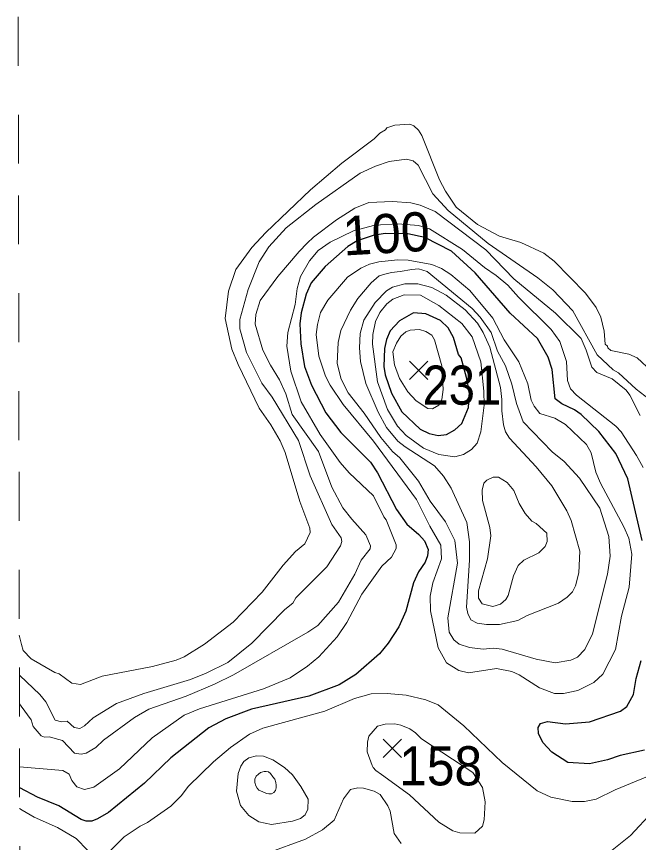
# Model space of a CAD drawing. Extents: x 474.5 to 500, y 7345.7 to 7373.4.
# Drawn here: x 474.546 to 475.818, y 7356.191 to 7357.879 of the extents above; entities that cross this region are included whole.
import ezdxf
from ezdxf.enums import TextEntityAlignment as Align

# ---------------------------------------------------------------- set-up
doc = ezdxf.new("R2010")
doc.units = 0
doc.header["$LTSCALE"] = 0.032
doc.linetypes.add('SHORT_DASHED', pattern=[2.7, 1.5, -1.2])
for name, color, linetype, lineweight in [('1', 7, 'Continuous', 25), ('2', 7, 'Continuous', 13), ('21', 7, 'Continuous', 25), ('22', 7, 'SHORT_DASHED', 13)]:
    doc.layers.add(name, color=color, linetype=linetype, lineweight=lineweight)
doc.layers.add('61', color=7, linetype='Continuous')

msp = doc.modelspace()

# ---------------------------------------------------------------- linework, layer by layer
at = {"layer": '1'}
for points in [[(475.8254, 7356.8079), (475.7963, 7356.9343), (475.7714, 7356.9858), (475.737, 7357.0305), (475.7007, 7357.0654), (475.6867, 7357.0751), (475.6613, 7357.0874), (475.6478, 7357.0975), (475.6411, 7357.1574), (475.6332, 7357.1824), (475.6113, 7357.2207), (475.5555, 7357.2725), (475.4841, 7357.3551), (475.4354, 7357.3994), (475.3811, 7357.4268), (475.3464, 7357.4348), (475.2997, 7357.4352), (475.2753, 7357.4312), (475.2428, 7357.4202), (475.2238, 7357.4089), (475.1773, 7357.3679), (475.1485, 7357.3348), (475.1382, 7357.3113), (475.1278, 7357.273), (475.1254, 7357.2507), (475.1272, 7357.2097), (475.1351, 7357.1636), (475.1495, 7357.1253), (475.1783, 7357.0687), (475.2092, 7357.0284), (475.2699, 7356.9678), (475.2839, 7356.946), (475.3229, 7356.8714), (475.3441, 7356.8411), (475.3684, 7356.8206), (475.3803, 7356.8072), (475.3877, 7356.7894), (475.3862, 7356.7768), (475.3815, 7356.7641), (475.3678, 7356.7438), (475.3577, 7356.7213), (475.342, 7356.6638), (475.3279, 7356.6314), (475.3058, 7356.5981), (475.288, 7356.5763), (475.2396, 7356.5342), (475.2057, 7356.5132), (475.1441, 7356.4903), (475.0267, 7356.4634), (474.9739, 7356.4437), (474.9392, 7356.4254), (474.8618, 7356.364), (474.8076, 7356.3121), (474.7345, 7356.2523), (474.7119, 7356.2391), (474.7001, 7356.2349), (474.6887, 7356.2349), (474.6783, 7356.2379), (474.6326, 7356.2659), (474.5887, 7356.2838), (474.5526, 7356.3028), (474.5524, 7356.3029)], [(475.8302, 7356.3797), (475.7806, 7356.369), (475.7547, 7356.3601), (475.7175, 7356.3515), (475.6732, 7356.3547), (475.6409, 7356.3756), (475.622, 7356.3955), (475.6135, 7356.414), (475.6129, 7356.4258), (475.6178, 7356.4342), (475.6319, 7356.4383), (475.6684, 7356.4336), (475.7178, 7356.4375), (475.7812, 7356.4596), (475.7943, 7356.4692), (475.8074, 7356.4936), (475.813, 7356.5263), (475.8235, 7356.5626)]]:
    msp.add_lwpolyline(points, dxfattribs=at)
msp.add_lwpolyline([(475.3289, 7357.2571), (475.3099, 7357.2366), (475.3024, 7357.2185), (475.2984, 7357.2006), (475.2972, 7357.1634), (475.3001, 7357.1464), (475.3125, 7357.1091), (475.334, 7357.0712), (475.3713, 7357.0357), (475.3897, 7357.027), (475.4082, 7357.0223), (475.425, 7357.0243), (475.4426, 7357.0341), (475.4564, 7357.047), (475.47, 7357.0798), (475.4721, 7357.111), (475.4665, 7357.1411), (475.455, 7357.1816), (475.4501, 7357.1883), (475.4399, 7357.2226), (475.4284, 7357.2424), (475.4128, 7357.2574), (475.383, 7357.2711), (475.3577, 7357.2735)], close=True, dxfattribs=at)
at = {"layer": '2'}
for points in [[(475.8443, 7357.1541), (475.8152, 7357.181), (475.798, 7357.1889), (475.7616, 7357.196), (475.7549, 7357.2017), (475.7545, 7357.2051), (475.75, 7357.2092), (475.7475, 7357.236), (475.7406, 7357.2643), (475.7315, 7357.2842), (475.7096, 7357.3131), (475.6457, 7357.3787), (475.6245, 7357.395), (475.5774, 7357.4172), (475.5339, 7357.4296), (475.4889, 7357.454), (475.4452, 7357.489), (475.4231, 7357.5216), (475.4112, 7357.5451), (475.3749, 7357.6352), (475.3682, 7357.6466), (475.3584, 7357.6555), (475.35, 7357.6588), (475.3197, 7357.6565), (475.3035, 7357.651), (475.3008, 7357.647), (475.2887, 7357.6404), (475.2771, 7357.6287), (475.211, 7357.5793), (475.1472, 7357.5244), (475.0561, 7357.4373), (475.0274, 7357.407), (474.9944, 7357.3619), (474.9794, 7357.3177), (474.973, 7357.2617), (474.9866, 7357.1991), (474.9991, 7357.1677), (475.0422, 7357.0784), (475.0663, 7357.0446), (475.0853, 7357.0114), (475.0954, 7356.9877), (475.1255, 7356.8876), (475.1459, 7356.833), (475.1467, 7356.8245), (475.1355, 7356.8012), (475.1167, 7356.7855), (475.0912, 7356.7576)], [(474.5519, 7356.5334), (474.5532, 7356.5322), (474.5937, 7356.4937), (474.606, 7356.4782), (474.6249, 7356.4411), (474.6381, 7356.4377), (474.6496, 7356.4391), (474.6637, 7356.4259), (474.6754, 7356.4241), (474.6851, 7356.4294), (474.7027, 7356.446), (474.7508, 7356.4753), (474.8063, 7356.4952), (474.902, 7356.524), (474.9339, 7356.5368), (474.9784, 7356.5591), (475.0276, 7356.5982), (475.0944, 7356.6674), (475.1108, 7356.6799), (475.1172, 7356.6911), (475.1803, 7356.7543), (475.2083, 7356.7974), (475.2115, 7356.8059), (475.2098, 7356.8133), (475.1905, 7356.8407), (475.1464, 7356.9401), (475.123, 7357.0125), (475.069, 7357.1008), (475.0476, 7357.1296), (475.0164, 7357.1922), (475.0025, 7357.2403), (475.0029, 7357.2595), (475.0201, 7357.321), (475.042, 7357.3773), (475.062, 7357.408), (475.0977, 7357.447), (475.1582, 7357.4947), (475.2486, 7357.5586), (475.2803, 7357.5731), (475.3083, 7357.5824), (475.3434, 7357.587), (475.3573, 7357.584), (475.3672, 7357.5749), (475.3973, 7357.5162), (475.4288, 7357.4824), (475.5107, 7357.4149), (475.6119, 7357.3447), (475.6426, 7357.3202), (475.6837, 7357.2775), (475.7334, 7357.1873), (475.766, 7357.157), (475.7768, 7357.1503), (475.8128, 7357.1174), (475.8398, 7357.0968)], [(475.4023, 7357.48), (475.3716, 7357.493), (475.3527, 7357.4977), (475.315, 7357.5009), (475.2665, 7357.4985), (475.2376, 7357.4872), (475.2006, 7357.4631), (475.1535, 7357.4276), (475.1403, 7357.4158), (475.1241, 7357.3984), (475.0801, 7357.3477), (475.0446, 7357.2981), (475.0352, 7357.2701), (475.0344, 7357.2502), (475.0495, 7357.1968), (475.0654, 7357.1661), (475.0841, 7357.1366), (475.097, 7357.1075), (475.1094, 7357.0656), (475.1638, 7356.9901), (475.1907, 7356.9173), (475.2133, 7356.8748), (475.2314, 7356.8515), (475.2603, 7356.8194), (475.2697, 7356.7974), (475.2694, 7356.7911), (475.251, 7356.7681), (475.2377, 7356.7396), (475.2047, 7356.6819), (475.1622, 7356.6347), (475.1418, 7356.6209), (474.9895, 7356.5335), (474.9509, 7356.5142), (474.8929, 7356.49), (474.8164, 7356.4637), (474.7873, 7356.4467), (474.7241, 7356.4), (474.7086, 7356.3852), (474.6884, 7356.3736), (474.6784, 7356.3714), (474.6645, 7356.3738), (474.6403, 7356.3992), (474.6129, 7356.4071), (474.6031, 7356.4065), (474.5963, 7356.409), (474.5804, 7356.4282), (474.5764, 7356.4416), (474.5558, 7356.4695), (474.5521, 7356.4746)], [(475.821, 7357.0635), (475.8004, 7357.105), (475.7928, 7357.115), (475.7637, 7357.1386), (475.7327, 7357.1514), (475.7224, 7357.1619), (475.7112, 7357.1968), (475.7005, 7357.2209), (475.6484, 7357.2723), (475.5633, 7357.3429), (475.506, 7357.4016), (475.4023, 7357.48)], [(474.5523, 7356.3459), (474.6409, 7356.3379), (474.6538, 7356.3305), (474.6593, 7356.318), (474.6696, 7356.3047), (474.6849, 7356.2996), (474.7041, 7356.3039), (474.7566, 7356.3416), (474.8234, 7356.4052), (474.889, 7356.4509), (474.92, 7356.464), (475.0509, 7356.5053), (475.1058, 7356.5278), (475.1414, 7356.5512), (475.1644, 7356.5707), (475.2016, 7356.611), (475.2217, 7356.6407), (475.252, 7356.6981), (475.2933, 7356.7554), (475.3129, 7356.7743), (475.3221, 7356.792), (475.3223, 7356.7992), (475.3022, 7356.8505), (475.2972, 7356.8563), (475.2759, 7356.899), (475.2263, 7356.946), (475.2082, 7356.9673), (475.1667, 7357.0249), (475.1283, 7357.0913), (475.107, 7357.1542), (475.0991, 7357.2049), (475.1008, 7357.2333), (475.1157, 7357.2904), (475.1198, 7357.3227), (475.1269, 7357.3475), (475.1455, 7357.3793), (475.1631, 7357.4006), (475.1874, 7357.4175), (475.2351, 7357.441), (475.2786, 7357.452), (475.326, 7357.4552), (475.3683, 7357.4516), (475.3907, 7357.4447), (475.458, 7357.4028), (475.5032, 7357.3655), (475.527, 7357.3497), (475.5508, 7357.33), (475.5722, 7357.3052), (475.6392, 7357.239), (475.6573, 7357.2144), (475.6704, 7357.1741), (475.6726, 7357.1352), (475.6791, 7357.1178), (475.6908, 7357.1051), (475.7718, 7357.0418), (475.7827, 7357.0301), (475.814, 7356.9818), (475.8271, 7356.9574)], [(475.0912, 7356.7576), (475.0487, 7356.7024), (474.9889, 7356.6409), (474.9306, 7356.5962), (474.889, 7356.5702), (474.8723, 7356.5633), (474.8239, 7356.5505), (474.7211, 7356.5309), (474.6772, 7356.5137), (474.6595, 7356.5165), (474.6333, 7356.5355), (474.6244, 7356.5385), (474.5761, 7356.5664), (474.5597, 7356.583), (474.5566, 7356.5955), (474.5518, 7356.6148)], [(474.7339, 7356.1709), (474.7659, 7356.2024), (474.799, 7356.2245), (474.8137, 7356.2317), (474.8614, 7356.2655), (474.8826, 7356.2866), (474.8981, 7356.306), (474.9486, 7356.3557), (474.9837, 7356.3853), (475.0222, 7356.4126), (475.0498, 7356.4248), (475.1766, 7356.4597), (475.2375, 7356.4854), (475.2711, 7356.4949), (475.3038, 7356.4957), (475.3429, 7356.4918), (475.3828, 7356.4823), (475.4083, 7356.4723), (475.4608, 7356.4291), (475.5391, 7356.3547), (475.6108, 7356.2968), (475.6386, 7356.284), (475.6824, 7356.2748), (475.7075, 7356.2748), (475.7311, 7356.2796), (475.7702, 7356.2985), (475.8673, 7356.3391)], [(475.3323, 7356.1889), (475.3186, 7356.2096), (475.3104, 7356.2548), (475.3055, 7356.2663), (475.2896, 7356.289), (475.2775, 7356.2956), (475.2556, 7356.3019), (475.244, 7356.3027), (475.2293, 7356.2996), (475.2145, 7356.2801), (475.1955, 7356.2364), (475.1719, 7356.2168), (475.1371, 7356.1981), (475.0585, 7356.1692)], [(474.5524, 7356.2602), (474.5574, 7356.2573), (474.5823, 7356.2426), (474.6301, 7356.222), (474.6682, 7356.1992), (474.6922, 7356.1746)], [(475.847, 7356.2546), (475.8012, 7356.2055), (475.7536, 7356.1674)]]:
    msp.add_lwpolyline(points, dxfattribs=at)
for points in [[(475.276, 7357.0113), (475.2137, 7357.0862), (475.1874, 7357.1254), (475.1777, 7357.1438), (475.1645, 7357.1845), (475.1589, 7357.2289), (475.1613, 7357.2493), (475.1679, 7357.2737), (475.1824, 7357.299), (475.2231, 7357.3458), (475.2503, 7357.3644), (475.2681, 7357.3724), (475.287, 7357.3772), (475.325, 7357.3812), (475.3471, 7357.3805), (475.3952, 7357.3718), (475.4152, 7357.3636), (475.4343, 7357.3516), (475.4727, 7357.3187), (475.5198, 7357.2622), (475.5432, 7357.2179), (475.5733, 7357.1728), (475.5918, 7357.1281), (475.5983, 7357.0946), (475.6043, 7357.0824), (475.6162, 7357.0677), (475.6468, 7357.0579), (475.6686, 7357.0454), (475.7116, 7357.0039), (475.7213, 7356.9869), (475.7307, 7356.9478), (475.7404, 7356.9249), (475.7881, 7356.8359), (475.7979, 7356.813), (475.8042, 7356.78), (475.7986, 7356.7125), (475.7834, 7356.6533), (475.7709, 7356.5857), (475.7447, 7356.5351), (475.7265, 7356.5182), (475.6935, 7356.5017), (475.6644, 7356.4958), (475.6458, 7356.4958), (475.6157, 7356.5071), (475.5742, 7356.5334), (475.5588, 7356.5406), (475.5272, 7356.5468), (475.4706, 7356.5374), (475.4505, 7356.5426), (475.4251, 7356.5582), (475.4084, 7356.5889), (475.3926, 7356.6646), (475.3918, 7356.6942), (475.3971, 7356.7214), (475.415, 7356.7707), (475.4134, 7356.7987), (475.3909, 7356.8372), (475.3637, 7356.8917)], [(475.3301, 7356.9767), (475.3147, 7356.9898), (475.2908, 7357.0185), (475.2569, 7357.0685), (475.2244, 7357.1101), (475.2097, 7357.1374), (475.2015, 7357.17), (475.2036, 7357.2124), (475.2089, 7357.2371), (475.2289, 7357.2789), (475.2441, 7357.3028), (475.2713, 7357.3345), (475.2873, 7357.3487), (475.299, 7357.3524), (475.3129, 7357.3553), (475.3307, 7357.3578), (475.3541, 7357.3618), (475.3683, 7357.3629), (475.3858, 7357.3575), (475.4776, 7357.2819), (475.4942, 7357.2645), (475.5169, 7357.2331), (475.5296, 7357.1949), (475.5457, 7357.1647), (475.5586, 7357.1273), (475.5685, 7357.0877), (475.5818, 7357.0508), (475.6412, 7356.9889), (475.6659, 7356.9692), (475.6969, 7356.9357), (475.7387, 7356.8742), (475.7572, 7356.8159), (475.7596, 7356.7759), (475.7547, 7356.7396), (475.7237, 7356.6173), (475.7084, 7356.5852), (475.6931, 7356.5698), (475.6792, 7356.5634), (475.6476, 7356.558), (475.6085, 7356.5653), (475.5391, 7356.586), (475.5208, 7356.5883), (475.5001, 7356.586), (475.4721, 7356.5892), (475.4509, 7356.5961), (475.4403, 7356.6052), (475.4307, 7356.6208), (475.4277, 7356.6499), (475.4476, 7356.7617), (475.4422, 7356.8079), (475.423, 7356.8465), (475.392, 7356.8881), (475.368, 7356.9295)], [(475.3408, 7356.9992), (475.326, 7357.011), (475.3029, 7357.0387), (475.2854, 7357.0706), (475.2606, 7357.1291), (475.2497, 7357.1741), (475.2474, 7357.2016), (475.2489, 7357.231), (475.256, 7357.258), (475.2793, 7357.2941), (475.3027, 7357.3179), (475.3148, 7357.3259), (475.3398, 7357.3328), (475.3668, 7357.3327), (475.3952, 7357.3249), (475.4243, 7357.3096), (475.4632, 7357.2795), (475.4885, 7357.2518), (475.5001, 7357.2331), (475.5142, 7357.2032), (475.5358, 7357.1207), (475.5385, 7357.0959), (475.5381, 7357.073), (475.5418, 7357.0441), (475.546, 7357.0298), (475.5543, 7357.0173), (475.6086, 7356.9586), (475.6408, 7356.9199), (475.6715, 7356.8687), (475.6802, 7356.8487), (475.6981, 7356.7861), (475.6958, 7356.7417), (475.6892, 7356.7157), (475.6829, 7356.7032), (475.6718, 7356.692), (475.6546, 7356.6799), (475.59, 7356.655), (475.571, 7356.6449), (475.5334, 7356.6362), (475.5069, 7356.6362), (475.4881, 7356.6394), (475.4752, 7356.646), (475.4688, 7356.6587), (475.466, 7356.672), (475.4723, 7356.7681), (475.4724, 7356.8051), (475.4668, 7356.8446), (475.4351, 7356.9148), (475.4194, 7356.9397), (475.4005, 7356.9608)], [(475.274, 7357.2089), (475.2746, 7357.2287), (475.2803, 7357.2558), (475.2887, 7357.2741), (475.3035, 7357.2914), (475.3157, 7357.3009), (475.3384, 7357.3102), (475.3718, 7357.3094), (475.4099, 7357.2881), (475.4569, 7357.2516), (475.4778, 7357.2244), (475.4956, 7357.1733), (475.5019, 7357.1129), (475.5025, 7357.0845), (475.4954, 7357.0303), (475.4879, 7357.0072), (475.4767, 7356.9939), (475.4603, 7356.984), (475.4423, 7356.9793), (475.4096, 7356.984), (475.3783, 7356.9967), (475.3425, 7357.0228), (475.3254, 7357.042), (475.3046, 7357.0754), (475.2841, 7357.1323)], [(475.3321, 7357.2253), (475.3423, 7357.2343), (475.3513, 7357.2377), (475.3702, 7357.2392), (475.3828, 7357.2353), (475.3955, 7357.2274), (475.4006, 7357.2183), (475.4157, 7357.1652), (475.4183, 7357.1163), (475.4159, 7357.096), (475.4093, 7357.0843), (475.3969, 7357.0769), (475.3874, 7357.0775), (475.3636, 7357.0934), (475.3464, 7357.1115), (475.3292, 7357.1392), (475.3189, 7357.1667), (475.3159, 7357.1938), (475.3228, 7357.2113)], [(475.6089, 7356.843), (475.5999, 7356.8477), (475.5863, 7356.8629), (475.5741, 7356.8839), (475.5628, 7356.9101), (475.5495, 7356.9267), (475.5317, 7356.9376), (475.5206, 7356.9378), (475.508, 7356.9316), (475.5014, 7356.9253), (475.4982, 7356.9111), (475.4986, 7356.8899), (475.5138, 7356.8343), (475.5162, 7356.8175), (475.5091, 7356.7704), (475.4906, 7356.7054), (475.4908, 7356.6902), (475.498, 7356.6785), (475.5202, 7356.6729), (475.5356, 7356.6782), (475.5465, 7356.6874), (475.5512, 7356.6957), (475.5624, 7356.7361), (475.5715, 7356.757), (475.5833, 7356.7681), (475.6141, 7356.7828), (475.6271, 7356.7959), (475.6312, 7356.8058), (475.6305, 7356.823)], [(475.4989, 7356.3033), (475.4793, 7356.3341), (475.3739, 7356.4026), (475.3618, 7356.4154), (475.3505, 7356.4234), (475.3319, 7356.4311), (475.3194, 7356.4335), (475.2998, 7356.4327), (475.2841, 7356.4287), (475.2666, 7356.4086), (475.2637, 7356.396), (475.2634, 7356.3762), (475.2735, 7356.3481), (475.2753, 7356.3443), (475.2809, 7356.3382), (475.2922, 7356.3303), (475.3498, 7356.2881), (475.4093, 7356.2325), (475.4382, 7356.2152), (475.4523, 7356.2109), (475.4832, 7356.2102), (475.4986, 7356.2246), (475.5026, 7356.2373), (475.5042, 7356.2744)], [(475.0108, 7356.3566), (475.0211, 7356.3642), (475.0367, 7356.3681), (475.0514, 7356.3674), (475.0705, 7356.36), (475.0938, 7356.3445), (475.1103, 7356.3296), (475.1277, 7356.3058), (475.1426, 7356.2793), (475.142, 7356.2591), (475.1363, 7356.2476), (475.1266, 7356.2403), (475.1105, 7356.2343), (475.0674, 7356.2278), (475.0418, 7356.2332), (475.0214, 7356.2462), (475.0042, 7356.2666), (474.9962, 7356.2961), (474.9993, 7356.3317), (475.0046, 7356.3468)], [(475.0573, 7356.2913), (475.0495, 7356.2947), (475.0419, 7356.2981), (475.038, 7356.3022), (475.0352, 7356.3069), (475.0336, 7356.3137), (475.0336, 7356.3205), (475.0362, 7356.3267), (475.0409, 7356.3309), (475.0451, 7356.334), (475.0524, 7356.3361), (475.0565, 7356.3361), (475.0615, 7356.3353), (475.0654, 7356.3322), (475.0703, 7356.3254), (475.074, 7356.3205), (475.0763, 7356.3134), (475.0771, 7356.308), (475.0768, 7356.3025), (475.0755, 7356.2976), (475.0722, 7356.2934), (475.0675, 7356.2908), (475.0617, 7356.2903)]]:
    msp.add_lwpolyline(points, close=True, dxfattribs=at)
at = {"layer": '21'}
for p, q in [((475.3496, 7357.1747), (475.3871, 7357.1372)), ((475.3871, 7357.1747), (475.3496, 7357.1372)), ((475.296, 7356.4021), (475.3335, 7356.3646)), ((475.3335, 7356.4021), (475.296, 7356.3646))]:
    msp.add_line(p, q, dxfattribs=at)
at = {"layer": '22'}
msp.add_lwpolyline([(474.5591, 7352.4942), (474.5581, 7353.059), (474.5571, 7353.6239), (474.5561, 7354.1888), (474.5551, 7354.7537), (474.5541, 7355.3185), (474.5531, 7355.8834), (474.5521, 7356.4483), (474.5511, 7357.0132), (474.5501, 7357.578), (474.5491, 7358.1429), (474.5481, 7358.7078), (474.5471, 7359.2727), (474.5461, 7359.8375)], dxfattribs=at)

# ---------------------------------------------------------------- texts
at = {"layer": '61'}
msp.add_text('100', height=0.08, rotation=3.282, dxfattribs=at).set_placement((475.3043, 7357.3953), align=Align.CENTER)
for s, width, p in [('231', 0.9, (475.4567, 7357.0855)), ('158', 0.95, (475.4133, 7356.3077))]:
    msp.add_text(s, height=0.08, dxfattribs=dict(at, width=width)).set_placement(p, align=Align.CENTER)

doc.saveas('drawing.dxf')
